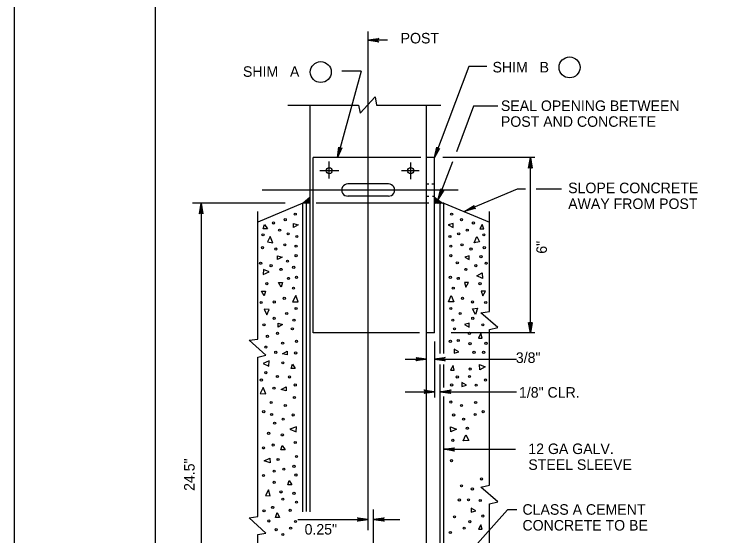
# Model space of a CAD drawing. Extents: x 648590 to 650336, y 294467 to 295061.
# Drawn here: x 648590.1 to 648794.7, y 294607.2 to 294755.5 of the extents above; entities that cross this region are included whole.
import ezdxf

# ---------------------------------------------------------------- set-up
doc = ezdxf.new("R2010")
doc.units = 0
for name, color, linetype in [('1', 7, 'Continuous'), ('2', 7, 'Continuous'), ('3', 7, 'Continuous'), ('PLT-BNDY', 7, 'Continuous')]:
    doc.layers.add(name, color=color, linetype=linetype)

msp = doc.modelspace()

# ---------------------------------------------------------------- linework, layer by layer
at = {"layer": '1'}
msp.add_line((648630.1, 295046.45), (648630.1, 294482.45), dxfattribs=at)
at = {"layer": '2'}
for p, q in [((648690.72, 294608.75), (648690.72, 294750.62)), ((648688.47, 294727.37), (648692.72, 294732)), ((648692.72, 294732), (648693.1, 294729.62)), ((648667.85, 294729.62), (648687.97, 294729.62)), ((648674.22, 294613.98), (648674.22, 294729.62)), ((648687.97, 294729.62), (648688.47, 294727.37)), ((648693.1, 294729.62), (648711.35, 294729.62)), ((648707.35, 294553.12), (648707.35, 294729.62)), ((648705.72, 294714.75), (648675.1, 294714.75)), ((648675.1, 294664.87), (648675.1, 294714.75)), ((648709.6, 294714.75), (648707.35, 294714.75)), ((648709.6, 294664.87), (648709.6, 294714.75)), ((648679.6, 294708.75), (648679.6, 294713.62)), ((648702.85, 294708.62), (648702.85, 294713.37)), ((648682.35, 294711), (648676.97, 294711)), ((648705.22, 294711), (648700.22, 294711)), ((648696.47, 294707.25), (648684.97, 294707.25)), ((648707.35, 294707.25), (648707.97, 294707.25)), ((648708.85, 294707.25), (648709.6, 294707.25)), ((648716.35, 294705.5), (648660.6, 294705.5)), ((648696.47, 294703.75), (648684.97, 294703.75)), ((648707.35, 294703.75), (648707.97, 294703.75)), ((648708.97, 294703.75), (648709.6, 294703.75)), ((648672.1, 294701.75), (648659.35, 294696.37)), ((648674.22, 294701.75), (648672.1, 294701.75)), ((648672.1, 294613.98), (648672.1, 294701.75)), ((648674.22, 294703.5), (648672.22, 294701.75)), ((648674.22, 294703.25), (648672.47, 294701.75)), ((648674.22, 294702.87), (648672.72, 294701.75)), ((648674.22, 294702.62), (648673.1, 294701.87)), ((648673.22, 294614.07), (648673.22, 294701.75)), ((648674.22, 294702.37), (648673.35, 294701.75)), ((648674.22, 294702.12), (648673.72, 294701.87)), ((648674.22, 294701.87), (648673.97, 294701.75)), ((648707.97, 294701.75), (648675.97, 294701.75)), ((648709.6, 294703.5), (648711.85, 294701.75)), ((648709.6, 294703.25), (648711.47, 294701.75)), ((648709.6, 294702.87), (648711.1, 294701.75)), ((648709.6, 294702.62), (648710.72, 294701.75)), ((648709.6, 294702.37), (648710.47, 294701.75)), ((648709.6, 294702.12), (648710.1, 294701.75)), ((648709.6, 294701.87), (648709.72, 294701.75)), ((648712.22, 294701.75), (648709.6, 294701.75)), ((648711.22, 294659), (648711.22, 294701.75)), ((648712.22, 294701.75), (648725.22, 294696.37)), ((648712.22, 294659), (648712.22, 294701.75)), ((648659.35, 294663.12), (648659.35, 294699.37)), ((648725.22, 294671), (648725.22, 294699.37)), ((648722.72, 294670.62), (648725.22, 294671)), ((648727.6, 294666.37), (648722.72, 294670.62)), ((648705.35, 294664.87), (648675.1, 294664.87)), ((648709.6, 294664.87), (648707.35, 294664.87)), ((648725.22, 294665.87), (648727.6, 294666.37)), ((648725.22, 294621.5), (648725.22, 294665.87)), ((648656.85, 294662.75), (648659.35, 294663.12)), ((648661.6, 294658.5), (648656.85, 294662.75)), ((648659.35, 294658), (648661.6, 294658.5)), ((648659.35, 294612.62), (648659.35, 294658)), ((648711.22, 294534.62), (648711.22, 294655.87)), ((648712.22, 294649.37), (648712.22, 294655.87)), ((648712.22, 294534.62), (648712.22, 294646.75)), ((648722.72, 294621), (648725.22, 294621.5)), ((648727.6, 294616.75), (648722.72, 294621)), ((648725.22, 294616.25), (648727.6, 294616.75)), ((648725.22, 294577.5), (648725.22, 294616.25)), ((648692.22, 294585.12), (648692.22, 294614.62)), ((648656.85, 294612.25), (648659.35, 294612.62)), ((648661.6, 294607.87), (648656.85, 294612.25)), ((648659.35, 294607.5), (648661.6, 294607.87)), ((648659.35, 294563.37), (648659.35, 294607.5))]:
    msp.add_line(p, q, dxfattribs=at)
for points in [[(648662.1, 294694.5), (648660.85, 294694.5), (648661.22, 294695.75)], [(648669.47, 294694.87), (648669.47, 294696), (648670.85, 294695.62)], [(648714.85, 294694.87), (648714.85, 294696), (648713.47, 294695.62)], [(648722.47, 294694.5), (648723.6, 294694.5), (648723.1, 294695.75)], [(648662.1, 294690.75), (648663.6, 294690.5), (648662.85, 294692.25)], [(648722.35, 294690.75), (648720.85, 294690.5), (648721.6, 294692.25)], [(648664.97, 294685.75), (648664.97, 294686.75), (648666.22, 294686.37)], [(648719.47, 294685.75), (648719.47, 294686.75), (648718.22, 294686.37)], [(648660.97, 294682.87), (648660.85, 294681.5), (648662.6, 294682.25)], [(648723.1, 294682), (648723.22, 294680.37), (648721.6, 294681.12)], [(648665.22, 294679.25), (648666.35, 294679.25), (648665.97, 294677.87)], [(648719.22, 294679.25), (648718.1, 294679.25), (648718.47, 294677.87)], [(648660.35, 294676.75), (648661.47, 294676.75), (648661.1, 294675.37)], [(648669.22, 294673.75), (648670.85, 294673.75), (648670.1, 294675.5)], [(648715.1, 294673.75), (648713.6, 294673.75), (648714.35, 294675.5)], [(648724.1, 294676.75), (648722.85, 294676.75), (648723.35, 294675.37)], [(648662.6, 294671.5), (648661.1, 294671.62), (648661.85, 294670)], [(648720.35, 294671.75), (648721.85, 294671.87), (648721.22, 294670.12)], [(648665.1, 294666.5), (648665.1, 294667.62), (648666.35, 294667.25)], [(648719.47, 294666.5), (648719.47, 294667.62), (648718.1, 294667.25)], [(648722.1, 294663.37), (648723.1, 294663.37), (648722.72, 294664.75)], [(648667.72, 294659.62), (648667.72, 294658.62), (648666.35, 294658.87)], [(648715.22, 294660.25), (648715.22, 294659.12), (648716.47, 294659.5)], [(648662.47, 294655.37), (648662.6, 294656.87), (648660.85, 294656.12)], [(648669.97, 294654.75), (648668.85, 294654.75), (648669.22, 294656)], [(648714.1, 294654.25), (648715.22, 294654.25), (648714.85, 294655.62)], [(648722.47, 294654.37), (648722.35, 294655.87), (648723.97, 294655.25)], [(648717.35, 294650.75), (648717.35, 294649.62), (648718.72, 294650)], [(648659.97, 294647.62), (648661.6, 294647.5), (648660.85, 294649.37)], [(648667.35, 294649.5), (648667.35, 294648.37), (648665.97, 294648.75)], [(648670.22, 294636.75), (648670.35, 294638.12), (648668.47, 294637.5)], [(648714.22, 294636.75), (648714.1, 294638.12), (648715.85, 294637.5)], [(648719.35, 294634.25), (648717.72, 294634.12), (648718.47, 294635.87)], [(648667.1, 294631.62), (648665.85, 294631.62), (648666.22, 294632.87)], [(648662.72, 294629.25), (648662.85, 294627.87), (648661.1, 294628.5)], [(648668.97, 294621.62), (648667.85, 294621.62), (648668.22, 294622.87)], [(648661.47, 294618.62), (648662.85, 294618.5), (648662.35, 294620.25)], [(648665.47, 294612.37), (648664.35, 294612.37), (648664.85, 294613.75)], [(648719.97, 294615), (648719.97, 294613.87), (648721.35, 294614.25)], [(648722.1, 294609), (648723.1, 294609), (648722.72, 294610.25)]]:
    msp.add_lwpolyline(points, close=True, dxfattribs=at)
for centre, radius in [((648679.63, 294711.01), 0.856), ((648702.8, 294711.01), 0.856), ((648669.98, 294698.65), 0.301), ((648714.45, 294698.65), 0.301), ((648663.77, 294696.14), 0.301), ((648667.14, 294697.08), 0.301), ((648717.28, 294697.08), 0.301), ((648720.65, 294696.14), 0.301), ((648665.53, 294694.12), 0.301), ((648667.95, 294693.04), 0.301), ((648716.47, 294693.04), 0.301), ((648718.9, 294694.12), 0.301), ((648660.81, 294692.77), 0.301), ((648670.45, 294692.27), 0.301), ((648713.97, 294692.27), 0.301), ((648723.61, 294692.77), 0.301), ((648660.68, 294689.13), 0.301), ((648667.01, 294689.94), 0.301), ((648670.21, 294689.55), 0.301), ((648714.21, 294689.55), 0.301), ((648717.41, 294689.94), 0.301), ((648723.75, 294689.13), 0.301), ((648664.45, 294688.73), 0.301), ((648719.97, 294688.73), 0.301), ((648667.76, 294685.27), 0.301), ((648670.21, 294686.83), 0.301), ((648714.21, 294686.83), 0.301), ((648722.8, 294686.57), 0.301), ((648660.13, 294684.68), 0.301), ((648663.1, 294684.01), 0.301), ((648665.93, 294682.93), 0.301), ((648669.54, 294683.52), 0.301), ((648716.07, 294684.82), 0.301), ((648718.49, 294682.93), 0.301), ((648721.32, 294684.01), 0.301), ((648724.29, 294684.68), 0.301), ((648661.89, 294678.88), 0.301), ((648668.08, 294680.37), 0.301), ((648670.33, 294680.68), 0.301), ((648714.09, 294680.68), 0.301), ((648716.34, 294680.37), 0.301), ((648722.53, 294678.88), 0.301), ((648669.5, 294677.6), 0.301), ((648714.92, 294677.6), 0.301), ((648666.87, 294674.7), 0.301), ((648717.55, 294674.7), 0.301), ((648660.27, 294673.49), 0.301), ((648664.01, 294673.66), 0.301), ((648720.41, 294673.66), 0.301), ((648724.15, 294673.49), 0.301), ((648670.21, 294671.81), 0.301), ((648714.21, 294671.81), 0.301), ((648663.96, 294669), 0.301), ((648667.55, 294670.39), 0.301), ((648669.62, 294668.5), 0.301), ((648714.8, 294668.5), 0.301), ((648716.87, 294670.39), 0.301), ((648720.46, 294669), 0.301), ((648661.08, 294667.15), 0.301), ((648723.34, 294667.15), 0.301), ((648664.91, 294664.73), 0.301), ((648669.15, 294666.02), 0.301), ((648715.27, 294666.02), 0.301), ((648719.51, 294664.73), 0.301), ((648662.06, 294663.89), 0.301), ((648670.33, 294662.47), 0.301), ((648714.09, 294662.47), 0.301), ((648716.34, 294662.7), 0.301), ((648661.62, 294660.83), 0.301), ((648666.39, 294661.92), 0.301), ((648719.69, 294661.8), 0.301), ((648724.22, 294661.9), 0.301), ((648664.43, 294659.32), 0.301), ((648670.09, 294659.16), 0.301), ((648720.82, 294659.32), 0.301), ((648723.55, 294659.35), 0.301), ((648666.47, 294656.37), 0.301), ((648719.73, 294654.59), 0.301), ((648661.62, 294653.54), 0.301), ((648664.9, 294652.46), 0.301), ((648668.36, 294652.32), 0.301), ((648716.07, 294652.32), 0.301), ((648719.52, 294652.46), 0.301), ((648660.34, 294651.45), 0.301), ((648669.98, 294650.05), 0.301), ((648714.45, 294650.05), 0.301), ((648724.08, 294651.45), 0.301), ((648663.92, 294649.15), 0.301), ((648721.44, 294649.98), 0.301), ((648669.74, 294646.5), 0.301), ((648663.13, 294645.06), 0.301), ((648667.15, 294644.23), 0.301), ((648714.21, 294645.2), 0.301), ((648717.27, 294644.23), 0.301), ((648721.29, 294645.06), 0.301), ((648661, 294642.45), 0.301), ((648723.42, 294642.45), 0.301), ((648663.25, 294641.63), 0.301), ((648666.56, 294640.33), 0.301), ((648669.39, 294641.51), 0.301), ((648715.03, 294641.51), 0.301), ((648717.86, 294640.33), 0.301), ((648721.17, 294641.63), 0.301), ((648664.12, 294639.16), 0.301), ((648662.41, 294636.29), 0.301), ((648666.32, 294635.83), 0.301), ((648718.93, 294637.73), 0.301), ((648669.98, 294633.7), 0.301), ((648714.79, 294634.3), 0.301), ((648660.96, 294632.13), 0.301), ((648663.71, 294632.96), 0.301), ((648670.34, 294629.69), 0.301), ((648665.09, 294628.83), 0.301), ((648714.44, 294628.5), 0.301), ((648663.99, 294625.53), 0.301), ((648666.74, 294626.08), 0.301), ((648669.62, 294626.91), 0.301), ((648660.96, 294624.29), 0.301), ((648670.17, 294624.43), 0.301), ((648663.99, 294622.36), 0.301), ((648722.94, 294623.3), 0.301), ((648665.91, 294619.61), 0.301), ((648717.27, 294621.37), 0.301), ((648720.35, 294620.46), 0.301), ((648666.46, 294617.54), 0.301), ((648669.62, 294619.2), 0.301), ((648716.65, 294617.32), 0.301), ((648719.25, 294617.36), 0.301), ((648670.31, 294616.72), 0.301), ((648722.6, 294617.18), 0.301), ((648661.1, 294614.24), 0.301), ((648663.57, 294615.21), 0.301), ((648668.52, 294614.38), 0.301), ((648662.47, 294611.35), 0.301), ((648670.04, 294611.21), 0.301), ((648715.26, 294612.54), 0.301), ((648723.34, 294612.76), 0.301), ((648668.66, 294609.29), 0.301), ((648718.03, 294609.3), 0.301), ((648719.62, 294611.16), 0.301), ((648664.54, 294608.87), 0.301), ((648666.46, 294607.5), 0.301), ((648714.09, 294608.07), 0.301)]:
    msp.add_circle(centre, radius, dxfattribs=at)
for centre, start, end in [((648684.94, 294705.52), 89.2551, 271.9772), ((648696.49, 294705.52), 268.0228, 90.7449)]:
    msp.add_arc(centre, 1.74, start, end, dxfattribs=at)
at = {"layer": '3'}
for p, q in [((648696.22, 294748.12), (648690.72, 294748.12)), ((648719.35, 294740.62), (648709.6, 294714.75)), ((648724.47, 294740.62), (648719.35, 294740.62)), ((648688.72, 294739.37), (648681.97, 294714.75)), ((648688.72, 294739.37), (648683.22, 294739.37)), ((648720.72, 294729.37), (648715.85, 294716.37)), ((648727.6, 294729.37), (648720.72, 294729.37)), ((648738.1, 294714.75), (648711.97, 294714.75)), ((648736.85, 294664.87), (648736.85, 294714.75)), ((648714.72, 294713.5), (648710.6, 294702.87)), ((648733.1, 294705.75), (648718.22, 294699.5)), ((648735.47, 294705.75), (648733.1, 294705.75)), ((648745.72, 294705.75), (648738.47, 294705.75)), ((648667.1, 294701.75), (648640.73, 294701.75)), ((648643.23, 294701.75), (648643.23, 294551.87)), ((648738.1, 294664.87), (648714.35, 294664.87)), ((648709.6, 294662.37), (648709.6, 294646.5)), ((648701.22, 294657.37), (648707.35, 294657.37)), ((648709.6, 294657.37), (648732.9, 294657.37)), ((648701.22, 294648.12), (648709.6, 294648.12)), ((648711.22, 294648.12), (648732.9, 294648.12)), ((648712.22, 294631.75), (648732.64, 294631.75)), ((648690.72, 294608.75), (648690.72, 294614.62)), ((648692.22, 294608.75), (648692.22, 294614.62)), ((648730.35, 294614.5), (648718.72, 294601.5)), ((648732.97, 294614.5), (648730.35, 294614.5)), ((648670.75, 294611.75), (648690.72, 294611.75)), ((648692.22, 294611.75), (648699.72, 294611.75))]:
    msp.add_line(p, q, dxfattribs=at)
for points in [[(648693.6, 294747.75), (648693.47, 294748), (648690.72, 294748.12), (648693.6, 294747.75), (648693.72, 294747.62), (648690.72, 294748.12), (648693.47, 294748.25), (648693.6, 294748.5), (648690.72, 294748.12), (648693.72, 294748.62), (648693.6, 294748.5)], [(648683.1, 294717.37), (648682.85, 294717.37), (648681.97, 294714.75), (648683.1, 294717.37), (648683.22, 294717.5), (648681.97, 294714.75), (648682.6, 294717.37), (648682.35, 294717.62), (648681.97, 294714.75), (648682.35, 294717.75), (648682.35, 294717.62)], [(648710.85, 294717.25), (648710.6, 294717.25), (648709.6, 294714.75), (648710.85, 294717.25), (648710.97, 294717.37), (648709.6, 294714.75), (648710.47, 294717.37), (648710.22, 294717.5), (648709.6, 294714.75), (648710.22, 294717.75), (648710.22, 294717.5)], [(648736.47, 294711.87), (648736.6, 294712), (648736.85, 294714.75), (648736.47, 294711.87), (648736.35, 294711.75), (648736.85, 294714.75), (648736.97, 294712), (648737.22, 294711.87), (648736.85, 294714.75), (648737.35, 294711.75), (648737.22, 294711.87)], [(648712.1, 294705.37), (648711.85, 294705.37), (648710.6, 294702.87), (648712.1, 294705.37), (648712.22, 294705.5), (648710.6, 294702.87), (648711.47, 294705.5), (648711.35, 294705.62), (648710.6, 294702.87), (648711.35, 294705.87), (648711.35, 294705.62)], [(648642.85, 294698.87), (648642.98, 294699), (648643.23, 294701.75), (648642.85, 294698.87), (648642.73, 294698.75), (648643.23, 294701.75), (648643.35, 294699), (648643.6, 294699), (648643.23, 294701.75), (648643.73, 294698.75), (648643.6, 294699)], [(648721.1, 294700.37), (648720.85, 294700.5), (648718.22, 294699.5), (648721.1, 294700.37), (648721.22, 294700.25), (648718.22, 294699.5), (648720.72, 294700.75), (648720.72, 294700.87), (648718.22, 294699.5), (648720.85, 294701.12), (648720.72, 294700.87)], [(648737.22, 294667.75), (648736.97, 294667.75), (648736.85, 294664.87), (648737.22, 294667.75), (648737.35, 294667.87), (648736.85, 294664.87), (648736.72, 294667.75), (648736.47, 294667.75), (648736.85, 294664.87), (648736.35, 294667.87), (648736.47, 294667.75)], [(648704.47, 294657.75), (648704.47, 294657.62), (648707.35, 294657.37), (648704.47, 294657.75), (648704.35, 294657.87), (648707.35, 294657.37), (648704.47, 294657.25), (648704.47, 294657.12), (648707.35, 294657.37), (648704.35, 294656.87), (648704.47, 294657.12)], [(648712.35, 294657), (648712.22, 294657.25), (648709.6, 294657.37), (648712.35, 294657), (648712.6, 294656.87), (648709.6, 294657.37), (648712.22, 294657.62), (648712.35, 294657.75), (648709.6, 294657.37), (648712.6, 294657.87), (648712.35, 294657.75)], [(648706.72, 294648.5), (648706.85, 294648.25), (648709.6, 294648.12), (648706.72, 294648.5), (648706.6, 294648.62), (648709.6, 294648.12), (648706.85, 294647.87), (648706.72, 294647.75), (648709.6, 294648.12), (648706.6, 294647.62), (648706.72, 294647.75)], [(648714.1, 294647.75), (648713.97, 294647.87), (648711.22, 294648.12), (648714.1, 294647.75), (648714.22, 294647.62), (648711.22, 294648.12), (648713.97, 294648.25), (648714.1, 294648.37), (648711.22, 294648.12), (648714.22, 294648.62), (648714.1, 294648.37)], [(648715.1, 294631.5), (648714.97, 294631.62), (648712.22, 294631.75), (648715.1, 294631.5), (648715.22, 294631.25), (648712.22, 294631.75), (648714.97, 294631.87), (648715.1, 294632), (648712.22, 294631.75), (648715.22, 294632.12), (648715.1, 294632)], [(648687.85, 294612.12), (648687.97, 294611.87), (648690.72, 294611.75), (648687.85, 294612.12), (648687.72, 294612.25), (648690.72, 294611.75), (648687.97, 294611.62), (648687.85, 294611.37), (648690.72, 294611.75), (648687.72, 294611.25), (648687.85, 294611.37)], [(648695.1, 294611.37), (648694.97, 294611.62), (648692.22, 294611.75), (648695.1, 294611.37), (648695.22, 294611.25), (648692.22, 294611.75), (648694.97, 294611.87), (648695.1, 294612.12), (648692.22, 294611.75), (648695.22, 294612.25), (648695.1, 294612.12)]]:
    msp.add_lwpolyline(points, dxfattribs=at)
for centre in [(648748, 294740.42), (648677.23, 294739.08)]:
    msp.add_circle(centre, 2.98, dxfattribs=at)
at = {"layer": 'PLT-BNDY'}
msp.add_lwpolyline([(648590.1, 295061.45), (649431.1, 295061.45), (649431.1, 294467.45), (648590.1, 294467.45)], close=True, dxfattribs=at)

# ---------------------------------------------------------------- texts
at = {"layer": '2'}
for s, p in [('  POST', (648697.72, 294747.23)), ('SHIM   A ', (648655.1, 294737.73)), ('SHIM   B ', (648726.1, 294738.98)), ('SEAL OPENING BETWEEN', (648728.47, 294728)), ('POST AND CONCRETE', (648728.47, 294723.5)), ('SLOPE CONCRETE', (648747.6, 294704.62)), ('AWAY FROM POST', (648747.6, 294700.12)), ('CLASS A CEMENT', (648734.6, 294613.12)), ('CONCRETE TO BE', (648734.6, 294608.62))]:
    msp.add_text(s, height=3, dxfattribs=at).set_placement(p)
at = {"layer": '3'}
for s, p in [('6"', (648741.55, 294687.4)), ('24.5"', (648641.36, 294619.9))]:
    msp.add_text(s, height=3, rotation=90, dxfattribs=at).set_placement(p)
for s, p in [(' 3/8"', (648731.61, 294656.32)), (' 1/8" CLR.', (648732.5, 294646.43)), ('12 GA GALV.', (648736.27, 294630.39)), ('STEEL SLEEVE', (648736.27, 294625.89)), ('0.25"', (648672.64, 294607.49))]:
    msp.add_text(s, height=3, dxfattribs=at).set_placement(p)

doc.saveas('drawing.dxf')
